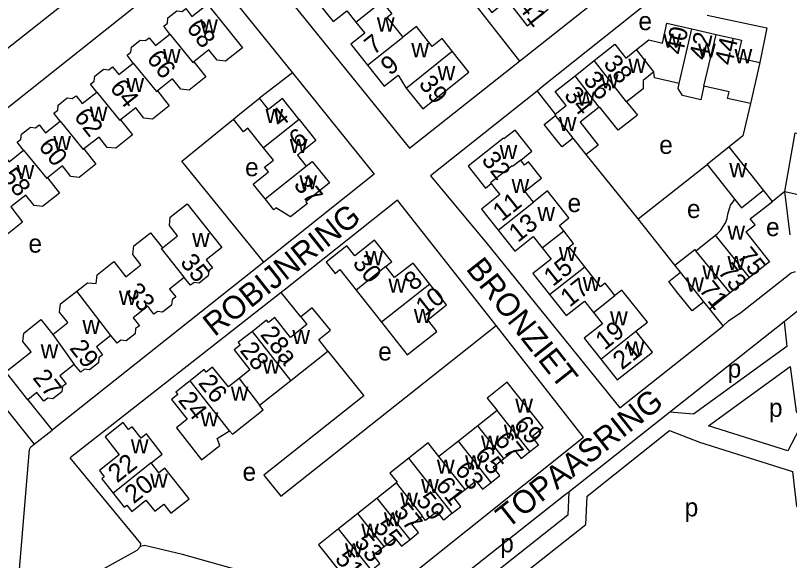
# Model space of a CAD drawing. Extents: x 159441 to 162086, y 388175 to 389787.
# Drawn here: x 160042 to 160211, y 388525.7 to 388644.7 of the extents above; entities that cross this region are included whole.
import ezdxf

# ---------------------------------------------------------------- set-up
doc = ezdxf.new("R2010")
doc.units = 0
for name, color, linetype in [('BLT_Basislijn', 7, 'Continuous'), ('BLT_Bebouwing', 7, 'Continuous'), ('BLT_Centroide', 7, 'Continuous'), ('BLT_Huisnummer', 7, 'Continuous'), ('BLT_Huisnummer_ tussenligend', 7, 'Continuous'), ('BLT_Onderverdeling_panden', 7, 'Continuous'), ('BLT_Straatnaam', 7, 'Continuous')]:
    doc.layers.add(name, color=color, linetype=linetype)

msp = doc.modelspace()

# ---------------------------------------------------------------- linework, layer by layer
at = {"layer": 'BLT_Basislijn'}
for p, q in [((160114.51, 388683.05), (160152.02, 388634.7)), ((160074.32, 388664.43), (160006.39, 388610.73)), ((160089.65, 388663.33), (160127.99, 388615.7)), ((160081.72, 388657.88), (160102.44, 388632.14)), ((160127.99, 388615.7), (160152.02, 388634.7)), ((160102.44, 388632.14), (160095.24, 388626.61)), ((160102.44, 388632.14), (160120.25, 388610.01)), ((160155.86, 388628.2), (160132.61, 388609.65)), ((160155.86, 388628.2), (160159.8, 388623.14)), ((160177.9, 388600.31), (160166.57, 388614.34)), ((160177.9, 388600.31), (160192.99, 388612.19)), ((160120.25, 388610.01), (160096.21, 388590.82)), ((160209.93, 388606.24), (160207.2, 388604.11)), ((160146.91, 388577.02), (160125.39, 388604.34)), ((160185.94, 388590.16), (160177.9, 388600.31)), ((160096.21, 388590.82), (160049.97, 388554.14)), ((160099.95, 388584.2), (160053.89, 388548.11)), ((160104.26, 388578.89), (160099.95, 388584.2)), ((160196.47, 388576.94), (160193.53, 388580.57)), ((160184.77, 388558.08), (160209.78, 388577.86)), ((160099.92, 388539.7), (160146.91, 388577.02)), ((160165.99, 388552.61), (160146.91, 388577.02)), ((160044.66, 388560.79), (160049.97, 388554.14)), ((160162.79, 388540.71), (160184.77, 388558.08)), ((160046.02, 388551.08), (160049.97, 388554.14)), ((160119.41, 388515.48), (160165.99, 388552.61))]:
    msp.add_line(p, q, dxfattribs=at)
for points in [[(160152.02, 388634.7), (160193.32, 388667.49), (160211.99, 388663.39), (160212.23, 388663.34)], [(160013.45, 388603.34), (160013.95, 388603.74), (160067.62, 388646.28), (160081.72, 388657.88)], [(160180.06, 388647.54), (160156.98, 388629.1), (160155.86, 388628.2)], [(160193, 388644.77), (160205.99, 388641.99), (160204.45, 388634.42)], [(160202.41, 388625.45), (160200.76, 388618.41), (160197.81, 388616)], [(160096.21, 388590.82), (160078.27, 388612.87), (160089.55, 388622.04)], [(160209.93, 388606.24), (160212.18, 388619.06), (160220.9, 388616.96), (160303.08, 388597.8)], [(160132.61, 388609.65), (160144.64, 388595.23), (160173.92, 388558.99)], [(160125.39, 388604.34), (160100.9, 388584.94), (160099.95, 388584.2)], [(160196.47, 388576.94), (160197.62, 388578.05), (160200.3, 388579.86), (160211.32, 388588.52), (160212.22, 388588.81)], [(160209.78, 388577.86), (160212.7, 388580.17), (160213.08, 388580.09)], [(160209.78, 388577.86), (160210.36, 388572.42), (160190, 388557.63), (160184.77, 388558.08)], [(160173.92, 388558.99), (160195.91, 388576.4), (160196.47, 388576.94)], [(160110.18, 388571.41), (160118.01, 388561.65), (160096.17, 388544.28), (160099.92, 388539.7)], [(160211.1, 388568.01), (160212.4, 388558.24), (160213.96, 388556.07), (160210.6, 388549.66), (160193.28, 388555.06), (160211.1, 388568.01)], [(160038.46, 388560.45), (160038.5, 388560.48), (160046.02, 388551.08)], [(160191.31, 388551.49), (160211.63, 388545.15), (160212.45, 388537.47), (160220.7, 388533.74), (160217.89, 388521.08), (160210.44, 388517.12), (160205.4, 388518.53), (160180.3, 388505.08), (160179.18, 388498.88), (160164.67, 388490.61), (160140.91, 388501.82), (160138.29, 388511.25), (160166.47, 388533.51), (160166.75, 388539.71), (160184.75, 388554.07), (160191.31, 388551.49)], [(160042.82, 388517.23), (160042.45, 388518.56), (160045.07, 388549.89), (160045.32, 388550.52), (160046.02, 388551.08)], [(160069.29, 388528.74), (160069.32, 388529.37), (160053.89, 388548.11)], [(160162.79, 388540.71), (160162.56, 388535.57), (160134.64, 388513.47), (160129.96, 388514.74)], [(160129.96, 388514.74), (160162, 388540.08), (160162.79, 388540.71)], [(160069.29, 388528.74), (160068.45, 388527.87), (160057.7, 388521.87), (160050.49, 388517.35)], [(160119.41, 388515.48), (160078.46, 388526.99), (160070.12, 388528.98), (160069.29, 388528.74)]]:
    msp.add_lwpolyline(points, dxfattribs=at)
at = {"layer": 'BLT_Bebouwing'}
for p, q in [((160189.61, 388641.76), (160194.95, 388640.55)), ((160164.13, 388631.52), (160168.34, 388634.87)), ((160204.45, 388634.42), (160202.41, 388625.45)), ((160197.81, 388616), (160192.99, 388612.19)), ((160205.28, 388606.55), (160197.81, 388616)), ((160207.2, 388604.11), (160205.28, 388606.55)), ((160190.53, 388593.34), (160194.76, 388596.76)), ((160202.24, 388587.48), (160197.99, 388584.11)), ((160197.99, 388584.11), (160193.53, 388580.57)), ((160044.66, 388560.79), (160039.84, 388566.88)), ((160147.14, 388558.44), (160142.9, 388555.08)), ((160142.9, 388555.08), (160138.67, 388551.73)), ((160132.07, 388551.36), (160127.83, 388548)), ((160127.83, 388548), (160123.73, 388544.76)), ((160120.96, 388539.3), (160116.72, 388535.93)), ((160116.72, 388535.93), (160112.51, 388532.58))]:
    msp.add_line(p, q, dxfattribs=at)
for points in [[(160152.06, 388653.87), (160147.71, 388650.43), (160145.61, 388653.1), (160142.08, 388650.31), (160142.88, 388649.3), (160145.98, 388645.38), (160149.32, 388648.01), (160153.7, 388642.42), (160158.27, 388646.05)], [(160075.66, 388640.62), (160074.33, 388642.38), (160075.15, 388643.03), (160075.26, 388644.15), (160077.2, 388645.7), (160078.33, 388645.55), (160079.14, 388646.2), (160080.51, 388644.47), (160083.93, 388647.18), (160091.51, 388637.62), (160087.83, 388634.71), (160086, 388634.91), (160084.2, 388637.18), (160080.9, 388634.57)], [(160107.68, 388647.91), (160111.3, 388643.35), (160114.31, 388645.73), (160116.29, 388643.23)], [(160121.96, 388647.78), (160124.11, 388645.06), (160123.13, 388644.29), (160126.56, 388639.97)], [(160116.29, 388643.23), (160118.21, 388640.8), (160115.2, 388638.42), (160118.84, 388633.84)], [(160177.55, 388637.25), (160180.21, 388639.36), (160183.22, 388638.68), (160184.2, 388642.99), (160189.61, 388641.76)], [(160137.34, 388636.87), (160135.11, 388639.67), (160132.96, 388637.96), (160129.52, 388642.32), (160126.56, 388639.97)], [(160067.68, 388634.29), (160066.33, 388636.03), (160067.15, 388636.68), (160067.27, 388637.8), (160069.21, 388639.34), (160070.33, 388639.2), (160071.15, 388639.85), (160072.52, 388638.12), (160075.66, 388640.62)], [(160194.95, 388640.55), (160200.45, 388639.3), (160199.58, 388635.54), (160204.45, 388634.42)], [(160168.34, 388634.87), (160172.84, 388638.44), (160175.22, 388635.4), (160177.55, 388637.25)], [(160127.27, 388628.86), (160130.88, 388624.28), (160140.97, 388632.29), (160137.34, 388636.87)], [(160080.9, 388634.57), (160083.51, 388631.28), (160079.88, 388628.4), (160078.05, 388628.6), (160076.24, 388630.87), (160072.95, 388628.26)], [(160059.71, 388627.98), (160058.35, 388629.69), (160059.17, 388630.34), (160059.28, 388631.46), (160061.22, 388633), (160062.35, 388632.86), (160063.16, 388633.5), (160064.53, 388631.78), (160067.68, 388634.29)], [(160118.84, 388633.84), (160122.48, 388629.26), (160125.5, 388631.65), (160127.14, 388629.02), (160127.27, 388628.86)], [(160159.8, 388623.14), (160162.2, 388625.05), (160159.79, 388628.07), (160164.13, 388631.52)], [(160181.35, 388632.37), (160179.02, 388630.52), (160178.99, 388628.71), (160175.39, 388625.87)], [(160186.88, 388629.83), (160181.47, 388631.06), (160181.35, 388632.37)], [(160192.28, 388629.25), (160191.58, 388626.3), (160187.58, 388627.25), (160186.64, 388628.76), (160186.88, 388629.83)], [(160051.74, 388621.62), (160050.38, 388623.36), (160051.19, 388624.01), (160051.31, 388625.14), (160053.25, 388626.68), (160054.38, 388626.54), (160055.19, 388627.18), (160056.55, 388625.47), (160059.71, 388627.98)], [(160072.95, 388628.26), (160075.56, 388624.97), (160071.86, 388622.04), (160070.02, 388622.24), (160068.22, 388624.51), (160064.93, 388621.9)], [(160202.41, 388625.45), (160197.44, 388626.58), (160197.77, 388628.01), (160192.28, 388629.25)], [(160089.55, 388622.04), (160091.34, 388623.48), (160095.24, 388626.61)], [(160103.91, 388622), (160100.26, 388626.59), (160097.21, 388624.15), (160095.24, 388626.61)], [(160169.41, 388624.7), (160165.23, 388621.38), (160169.17, 388616.4), (160166.57, 388614.34)], [(160175.39, 388625.87), (160177.77, 388622.94), (160173.58, 388619.62), (160169.5, 388624.77), (160169.41, 388624.7)], [(160163.72, 388617.92), (160161.3, 388615.98), (160160.49, 388616.99), (160157.37, 388620.9), (160159.83, 388622.86)], [(160159.83, 388622.86), (160159.95, 388622.95), (160159.8, 388623.14)], [(160043.74, 388615.31), (160042.36, 388617.03), (160043.18, 388617.68), (160043.29, 388618.8), (160045.23, 388620.34), (160046.36, 388620.2), (160047.17, 388620.84), (160048.54, 388619.1), (160051.74, 388621.62)], [(160064.93, 388621.9), (160067.54, 388618.61), (160063.86, 388615.69), (160062.02, 388615.89), (160060.22, 388618.16), (160056.93, 388615.55)], [(160096.14, 388615.8), (160092.7, 388620.11), (160091.72, 388619.32), (160089.55, 388622.04)], [(160103.91, 388622), (160107.57, 388617.41), (160103.52, 388614.19), (160105.46, 388611.76)], [(160152.26, 388613.12), (160154.67, 388615.07), (160151.03, 388619.66), (160148.61, 388617.75), (160148.51, 388617.88), (160140.81, 388611.77), (160144.55, 388607.02), (160145.8, 388608)], [(160166.57, 388614.34), (160163.72, 388617.92)], [(160035.75, 388608.94), (160034.38, 388610.67), (160035.2, 388611.32), (160035.32, 388612.44), (160037.26, 388613.98), (160038.38, 388613.84), (160039.2, 388614.48), (160040.58, 388612.76), (160043.74, 388615.31)], [(160056.93, 388615.55), (160059.54, 388612.26), (160055.88, 388609.35), (160054.04, 388609.56), (160052.24, 388611.83), (160048.95, 388609.22)], [(160096.5, 388604.64), (160093.88, 388607.89), (160097.18, 388610.54), (160096.35, 388611.57), (160098.29, 388613.12), (160096.14, 388615.8)], [(160105.46, 388611.76), (160106.77, 388612.81), (160110.51, 388608.13), (160105.37, 388604.04), (160105.69, 388603.63), (160102.01, 388600.71), (160098.82, 388602.66), (160098.37, 388602.29), (160096.5, 388604.64)], [(160155.08, 388603.96), (160153.2, 388606.33), (160156.81, 388609.19), (160153.99, 388612.74), (160153.11, 388612.04), (160152.26, 388613.12)], [(160192.99, 388612.19), (160199.02, 388604.52)], [(160048.95, 388609.22), (160051.56, 388605.93), (160047.88, 388603.01), (160046.05, 388603.22), (160044.24, 388605.49), (160040.95, 388602.88)], [(160145.8, 388608), (160146.72, 388606.84)], [(160146.72, 388606.84), (160147.72, 388605.57), (160143.73, 388602.43), (160147.37, 388597.84)], [(160161.67, 388597.65), (160160.73, 388598.84), (160162.81, 388600.48), (160158.14, 388606.37), (160155.08, 388603.96)], [(160209.93, 388606.24), (160218.26, 388604.34), (160217.82, 388602.37), (160223.04, 388601.18), (160222.4, 388598.76)], [(160211.06, 388596.8), (160209.93, 388606.24)], [(160194.76, 388596.76), (160195.22, 388597.1), (160195.94, 388597.8), (160196.97, 388599.44), (160197.36, 388600.36), (160197.5, 388601.32), (160198.06, 388603.28), (160199.02, 388604.52)], [(160201.44, 388597.43), (160203.44, 388599.01), (160202.38, 388600.3), (160207.2, 388604.11)], [(160040.95, 388602.88), (160043.5, 388599.53), (160039.88, 388596.67), (160038.05, 388596.87), (160036.24, 388599.14), (160032.95, 388596.53)], [(160074.06, 388593.99), (160077.36, 388596.6), (160075.57, 388598.85), (160075.77, 388600.69), (160079.44, 388603.59), (160087.01, 388594.02), (160083.59, 388591.32), (160084.96, 388589.57), (160084.16, 388588.94), (160084.04, 388587.81), (160082.08, 388586.26), (160080.96, 388586.41), (160080.2, 388585.8), (160078.77, 388587.48)], [(160147.37, 388597.84), (160151.01, 388593.26), (160155, 388596.41), (160156.95, 388593.93)], [(160166.26, 388589.84), (160162.84, 388594.17), (160163.81, 388594.94), (160161.67, 388597.65)], [(160201.44, 388597.43), (160206.59, 388590.93), (160202.24, 388587.48)], [(160066.08, 388587.66), (160069.37, 388590.27), (160067.58, 388592.53), (160067.78, 388594.36), (160071.46, 388597.27), (160074.06, 388593.99)], [(160122.82, 388589.87), (160123.8, 388590.67), (160124.1, 388590.91), (160120.37, 388595.62), (160116.05, 388592.2), (160114.3, 388594.41), (160109.8, 388590.86), (160111.75, 388588.39), (160112.78, 388589.2), (160116.32, 388584.71)], [(160156.95, 388593.93), (160158.91, 388591.46), (160154.93, 388588.32), (160158.57, 388583.74)], [(160185.94, 388590.16), (160190.29, 388593.61), (160190.53, 388593.34)], [(160055.34, 388584.51), (160057.67, 388586.35), (160059.58, 388586.2), (160059.79, 388588.03), (160063.47, 388590.95), (160066.08, 388587.66)], [(160132.42, 388586.06), (160128.78, 388590.64), (160124.74, 388587.46), (160122.82, 388589.87)], [(160172.84, 388583.55), (160171.88, 388584.76), (160170.7, 388586.25), (160169.72, 388585.47), (160166.26, 388589.84)], [(160187.12, 388588.67), (160185.94, 388590.16)], [(160078.77, 388587.48), (160075.59, 388584.96), (160076.95, 388583.23), (160076.15, 388582.6), (160076.03, 388581.47), (160074.07, 388579.92), (160072.95, 388580.07), (160072.2, 388579.47), (160070.84, 388581.19)], [(160192.25, 388582.19), (160189.72, 388580.17), (160186.6, 388584.08), (160184.57, 388586.63), (160187.12, 388588.67)], [(160129.25, 388571.97), (160133.96, 388575.7), (160131.97, 388578.21), (160136.05, 388581.48), (160132.42, 388586.06)], [(160050.1, 388575.01), (160053.39, 388577.62), (160051.6, 388579.88), (160051.81, 388581.71), (160055.34, 388584.51)], [(160116.32, 388584.71), (160121.87, 388577.7)], [(160177.42, 388575.76), (160179.92, 388577.7), (160174.35, 388584.73), (160172.84, 388583.55)], [(160158.57, 388583.74), (160162.2, 388579.16), (160166.17, 388582.3), (160168.13, 388579.82)], [(160193.53, 388580.57), (160192.25, 388582.19)], [(160070.84, 388581.19), (160067.65, 388578.67), (160069.02, 388576.95), (160068.21, 388576.31), (160068.09, 388575.18), (160066.13, 388573.63), (160065.01, 388573.78), (160064.21, 388573.15), (160062.82, 388574.85)], [(160110.18, 388571.41), (160108.18, 388573.94), (160110.71, 388575.95), (160106.77, 388580.89), (160104.26, 388578.89)], [(160104.26, 388578.89), (160105.6, 388577.2), (160102.04, 388574.38), (160098.6, 388578.72), (160097.24, 388577.63), (160096.8, 388578.18), (160093.69, 388575.7)], [(160168.13, 388579.82), (160170.09, 388577.35), (160166.13, 388574.22), (160169.74, 388569.67)], [(160039.84, 388566.88), (160045.38, 388571.26), (160043.58, 388573.54), (160043.79, 388575.36), (160047.49, 388578.29), (160050.1, 388575.01)], [(160121.87, 388577.7), (160127.49, 388570.57), (160129.25, 388571.97)], [(160093.69, 388575.7), (160092, 388574.36), (160090.62, 388573.27), (160091.06, 388572.72), (160089.71, 388571.65), (160093.15, 388567.32), (160090.8, 388565.45)], [(160169.74, 388569.67), (160173.35, 388565.12), (160181.04, 388571.19), (160177.42, 388575.76)], [(160062.82, 388574.85), (160059.64, 388572.33), (160061, 388570.61), (160060.2, 388569.97), (160060.08, 388568.85), (160058.12, 388567.29), (160057, 388567.44), (160056.23, 388566.83), (160054.82, 388568.5)], [(160102.07, 388564.98), (160110.18, 388571.41)], [(160054.82, 388568.5), (160051.66, 388566.01), (160053.01, 388564.29), (160052.21, 388563.66), (160052.09, 388562.53), (160050.13, 388560.98), (160049.01, 388561.13), (160048.18, 388560.47), (160046.67, 388562.39), (160044.66, 388560.79)], [(160090.8, 388565.45), (160088.45, 388563.59), (160085, 388567.93), (160083.59, 388566.81), (160083.16, 388567.36), (160080.08, 388564.91)], [(160080.08, 388564.91), (160078.83, 388563.92), (160076.98, 388562.45), (160077.42, 388561.9), (160076.07, 388560.83), (160079.49, 388556.51), (160077.1, 388554.62), (160082.61, 388547.67), (160086.56, 388550.81), (160086.01, 388552.35), (160088.72, 388554.02)], [(160095.24, 388559.57), (160102.07, 388564.98)], [(160154.28, 388549.45), (160156.16, 388550.94), (160154.7, 388552.78), (160157.2, 388554.76), (160149.33, 388564.64), (160144.95, 388561.15), (160147.14, 388558.44)], [(160088.72, 388554.02), (160089.32, 388553.26), (160096.03, 388558.57), (160095.24, 388559.57)], [(160071.6, 388546.99), (160074.03, 388548.91), (160070.55, 388553.31), (160069.41, 388552.41), (160067.46, 388554.88), (160066.67, 388554.26), (160065.45, 388555.8), (160061.52, 388552.67), (160064.62, 388548.74), (160060.29, 388545.31), (160061.37, 388543.95), (160060.82, 388543.52), (160063.28, 388540.41)], [(160138.67, 388551.73), (160134.43, 388548.38)], [(160134.43, 388548.38), (160132.07, 388551.36)], [(160148.58, 388547.93), (160150.93, 388549.79), (160152.39, 388547.95), (160154.28, 388549.45)], [(160063.28, 388540.41), (160064.32, 388539.09), (160065.73, 388537.31), (160066.28, 388537.75), (160067.35, 388536.39), (160070.46, 388538.86), (160072.38, 388536.44), (160074.34, 388537.99), (160075.89, 388536.03), (160079.87, 388539.18), (160074.6, 388545.85), (160073.3, 388544.83), (160071.6, 388546.99)], [(160145.81, 388542.73), (160147.7, 388544.22), (160146.23, 388546.06), (160148.58, 388547.93)], [(160123.73, 388544.76), (160125.31, 388542.76), (160125.14, 388542.63)], [(160125.14, 388542.63), (160120.96, 388539.3)], [(160140.12, 388541.21), (160142.47, 388543.08), (160143.93, 388541.23), (160145.81, 388542.73)], [(160137.34, 388536.01), (160139.23, 388537.51), (160137.77, 388539.35), (160140.12, 388541.21)], [(160128.11, 388530.29), (160129.97, 388531.76), (160128.51, 388533.6), (160130.74, 388535.37)], [(160137.34, 388536.01), (160135.46, 388534.52), (160134, 388536.36), (160131.51, 388534.39), (160130.74, 388535.37)], [(160112.51, 388532.58), (160108.14, 388529.1), (160113.84, 388521.93), (160116.34, 388523.92), (160117.8, 388522.08), (160119.67, 388523.57)], [(160122.43, 388528.75), (160124.77, 388530.61), (160126.25, 388528.81), (160128.11, 388530.29)], [(160119.67, 388523.57), (160121.54, 388525.05), (160120.09, 388526.89), (160122.43, 388528.75)]]:
    msp.add_lwpolyline(points, dxfattribs=at)
at = {"layer": 'BLT_Onderverdeling_panden'}
for p, q in [((160116.29, 388643.23), (160121.96, 388647.78)), ((160186.88, 388629.83), (160189.61, 388641.76)), ((160118.84, 388633.84), (160126.56, 388639.97)), ((160192.28, 388629.25), (160194.95, 388640.55)), ((160127.27, 388628.86), (160137.34, 388636.87)), ((160181.35, 388632.37), (160177.55, 388637.25)), ((160175.39, 388625.87), (160168.34, 388634.87)), ((160169.41, 388624.7), (160164.13, 388631.52)), ((160163.72, 388617.92), (160159.83, 388622.86)), ((160103.91, 388622), (160096.14, 388615.8)), ((160096.5, 388604.64), (160105.46, 388611.76)), ((160200.48, 388602.71), (160205.28, 388606.55)), ((160147.37, 388597.84), (160155.08, 388603.96)), ((160156.95, 388593.93), (160161.67, 388597.65)), ((160202.24, 388587.48), (160194.76, 388596.76)), ((160197.99, 388584.11), (160190.53, 388593.34)), ((160122.82, 388589.87), (160116.32, 388584.71)), ((160158.57, 388583.74), (160166.26, 388589.84)), ((160192.25, 388582.19), (160187.12, 388588.67)), ((160132.42, 388586.06), (160121.87, 388577.7)), ((160062.82, 388574.85), (160055.34, 388584.51)), ((160168.13, 388579.82), (160172.84, 388583.55)), ((160102.07, 388564.98), (160093.69, 388575.7)), ((160169.74, 388569.67), (160177.42, 388575.76)), ((160050.1, 388575.01), (160054.82, 388568.5)), ((160090.8, 388565.45), (160095.24, 388559.57)), ((160088.72, 388554.02), (160080.08, 388564.91)), ((160154.28, 388549.45), (160147.14, 388558.44)), ((160148.58, 388547.93), (160142.9, 388555.08)), ((160145.81, 388542.73), (160138.67, 388551.73)), ((160140.12, 388541.21), (160134.43, 388548.38)), ((160071.6, 388546.99), (160063.28, 388540.41)), ((160137.34, 388536.01), (160127.83, 388548)), ((160128.11, 388530.29), (160120.96, 388539.3)), ((160122.43, 388528.75), (160116.72, 388535.93)), ((160119.67, 388523.57), (160112.51, 388532.58))]:
    msp.add_line(p, q, dxfattribs=at)
for points in [[(160075.66, 388640.62), (160080.71, 388634.42), (160080.9, 388634.57)], [(160067.68, 388634.29), (160072.73, 388628.08), (160072.95, 388628.26)], [(160059.71, 388627.98), (160064.76, 388621.76), (160064.93, 388621.9)], [(160051.74, 388621.62), (160056.78, 388615.43), (160056.93, 388615.55)], [(160043.74, 388615.31), (160048.8, 388609.1), (160048.95, 388609.22)], [(160152.26, 388613.12), (160150.51, 388611.73), (160150.42, 388611.85), (160145.71, 388608.12), (160145.8, 388608)], [(160199.02, 388604.52), (160200.48, 388602.71)], [(160078.77, 388587.48), (160078.83, 388587.52), (160073.85, 388593.81), (160074.06, 388593.99)], [(160130.74, 388535.37), (160130.84, 388535.45), (160125.14, 388542.63)]]:
    msp.add_lwpolyline(points, dxfattribs=at)

# ---------------------------------------------------------------- texts
at = {"layer": 'BLT_Centroide'}
for s, p in [('e', (160177.96, 388641.5)), ('w', (160082.3, 388640.78)), ('w', (160120.88, 388641.19)), ('w', (160183.4, 388637.69)), ('w', (160128.39, 388635.59)), ('w', (160190.98, 388635.48)), ('w', (160074.19, 388634.34)), ('w', (160198.95, 388634.28)), ('w', (160175.77, 388632.16)), ('w', (160134.12, 388630.56)), ('w', (160169.77, 388628.78)), ('w', (160066.2, 388628)), ('w', (160164.59, 388625)), ('w', (160058.2, 388621.69)), ('w', (160096.56, 388621.19)), ('w', (160160.61, 388619.48)), ('w', (160050.23, 388615.34)), ('w', (160101.86, 388614.64)), ('e', (160182.5, 388614.47)), ('w', (160147.66, 388613.34)), ('e', (160092.1, 388609.59)), ('w', (160042.23, 388609)), ('w', (160197.81, 388609.38)), ('w', (160103.96, 388606.75)), ('w', (160150.27, 388605.94)), ('e', (160162.49, 388601.77)), ('w', (160155.91, 388599.81)), ('e', (160188.56, 388600.47)), ('e', (160205.82, 388596.52)), ('w', (160197.39, 388595.76)), ('e', (160044.81, 388592.91)), ('w', (160080.53, 388594.14)), ('w', (160160.59, 388591.08)), ('w', (160118.34, 388590.16)), ('w', (160197.39, 388589.11)), ('w', (160191.91, 388587.09)), ('w', (160123.39, 388584.16)), ('w', (160165.81, 388584.5)), ('w', (160188.41, 388584.42)), ('w', (160064.56, 388581.5)), ('w', (160128.95, 388577.52)), ('w', (160171.78, 388577)), ('w', (160056.58, 388575.16)), ('w', (160102.42, 388572.94)), ('w', (160047.47, 388569.83)), ('e', (160121.15, 388569.36)), ('w', (160175.41, 388570.44)), ('w', (160095.89, 388566.5)), ('p', (160197.43, 388565.62)), ('w', (160088.98, 388560.59)), ('w', (160151.08, 388557.95)), ('p', (160206.46, 388557.04)), ('w', (160082.39, 388554.97)), ('w', (160148.59, 388552.28)), ('w', (160067.16, 388549.05)), ('w', (160143.62, 388549.84)), ('w', (160140.12, 388545.56)), ('w', (160133.97, 388544.61)), ('e', (160091.54, 388543.09)), ('w', (160071.37, 388541.56)), ('w', (160130.53, 388540.39)), ('w', (160125.98, 388537.44)), ('p', (160188.06, 388535.31)), ('w', (160122.41, 388533.11)), ('w', (160117.47, 388530.66)), ('p', (160147.79, 388527.47)), ('w', (160113.91, 388526.39))]:
    msp.add_text(s, height=4, dxfattribs=at).set_placement(p)
at = {"layer": 'BLT_Huisnummer'}
for s, rotation, p in [('41', 308.0611, (160151.51, 388646.56)), ('68', 308.2589, (160079.13, 388641.92)), ('44', 77.2158, (160198.41, 388633.62)), ('9', 38.4317, (160123.71, 388631.45)), ('38', 308.6042, (160170.15, 388634.12)), ('39', 308.2564, (160129.84, 388629.71)), ('34', 308.6042, (160161.56, 388627.22)), ('4', 38.5608, (160099.73, 388620.07)), ('62', 308.2589, (160054.57, 388622.56)), ('6', 38.5608, (160103.7, 388615.47)), ('32', 308.3896, (160143.55, 388613.09)), ('58', 308.2589, (160038.79, 388609.5)), ('37', 308.6046, (160102.54, 388607.67)), ('11', 38.4317, (160148.15, 388599.57)), ('75', 308.5453, (160199.33, 388592.1)), ('35', 308.3519, (160077.77, 388590.73)), ('30', 308.3098, (160115.41, 388590.57)), ('15', 38.4317, (160159.29, 388585.38)), ('8', 38.4201, (160128.82, 388584.39)), ('71', 308.5453, (160191.03, 388584.74)), ('10', 38.4201, (160131.35, 388578.9)), ('28a', 308.3693, (160095.25, 388574.95)), ('21', 38.4317, (160174.37, 388567.18)), ('27', 308.3519, (160045.57, 388565.54)), ('24', 308.3693, (160077.32, 388560.64)), ('69', 308.4977, (160150.55, 388555.33)), ('22', 38.3693, (160064.19, 388542.5)), ('63', 308.4977, (160137.7, 388545.4)), ('20', 38.3693, (160067.8, 388537.94)), ('59', 308.4977, (160129.23, 388538.71)), ('55', 308.4977, (160119.93, 388532.85)), ('51', 308.4977, (160111.54, 388526.02))]:
    msp.add_text(s, height=4, rotation=rotation, dxfattribs=at).set_placement(p)
at = {"layer": 'BLT_Huisnummer_ tussenligend'}
for s, rotation, p in [('40', 77.2158, (160187.6, 388635.94)), ('7', 38.4317, (160120.15, 388635.94)), ('42', 77.2158, (160192.85, 388634.74)), ('66', 308.2589, (160070.45, 388635.23)), ('36', 308.6042, (160165.75, 388630.57)), ('64', 308.2589, (160062.4, 388628.85)), ('60', 308.2589, (160046.83, 388616.09)), ('13', 38.4317, (160151.66, 388595)), ('73', 308.5453, (160195.15, 388588.65)), ('17', 38.4317, (160162.94, 388580.87)), ('33', 308.3519, (160065.9, 388584.35)), ('19', 38.4317, (160170.58, 388571.47)), ('29', 308.3519, (160053.62, 388572.01)), ('28', 308.3693, (160090.81, 388571.5)), ('26', 308.3693, (160081.71, 388564.4)), ('67', 308.4977, (160146.37, 388551.89)), ('65', 308.4977, (160142.09, 388548.74)), ('61', 308.4977, (160133.49, 388542.01)), ('57', 308.4977, (160124.32, 388536.32)), ('53', 308.4977, (160115.75, 388529.61))]:
    msp.add_text(s, height=4, rotation=rotation, dxfattribs=at).set_placement(p)
at = {"layer": 'BLT_Straatnaam'}
for s, rotation, p in [('ROBIJNRING', 38.3921, (160085.44, 388574.43)), ('BRONZIET', 308.3976, (160140.15, 388589.32)), ('TOPAASRING', 38.2873, (160149.38, 388532.48))]:
    msp.add_text(s, height=5, rotation=rotation, dxfattribs=at).set_placement(p)

doc.saveas('drawing.dxf')
